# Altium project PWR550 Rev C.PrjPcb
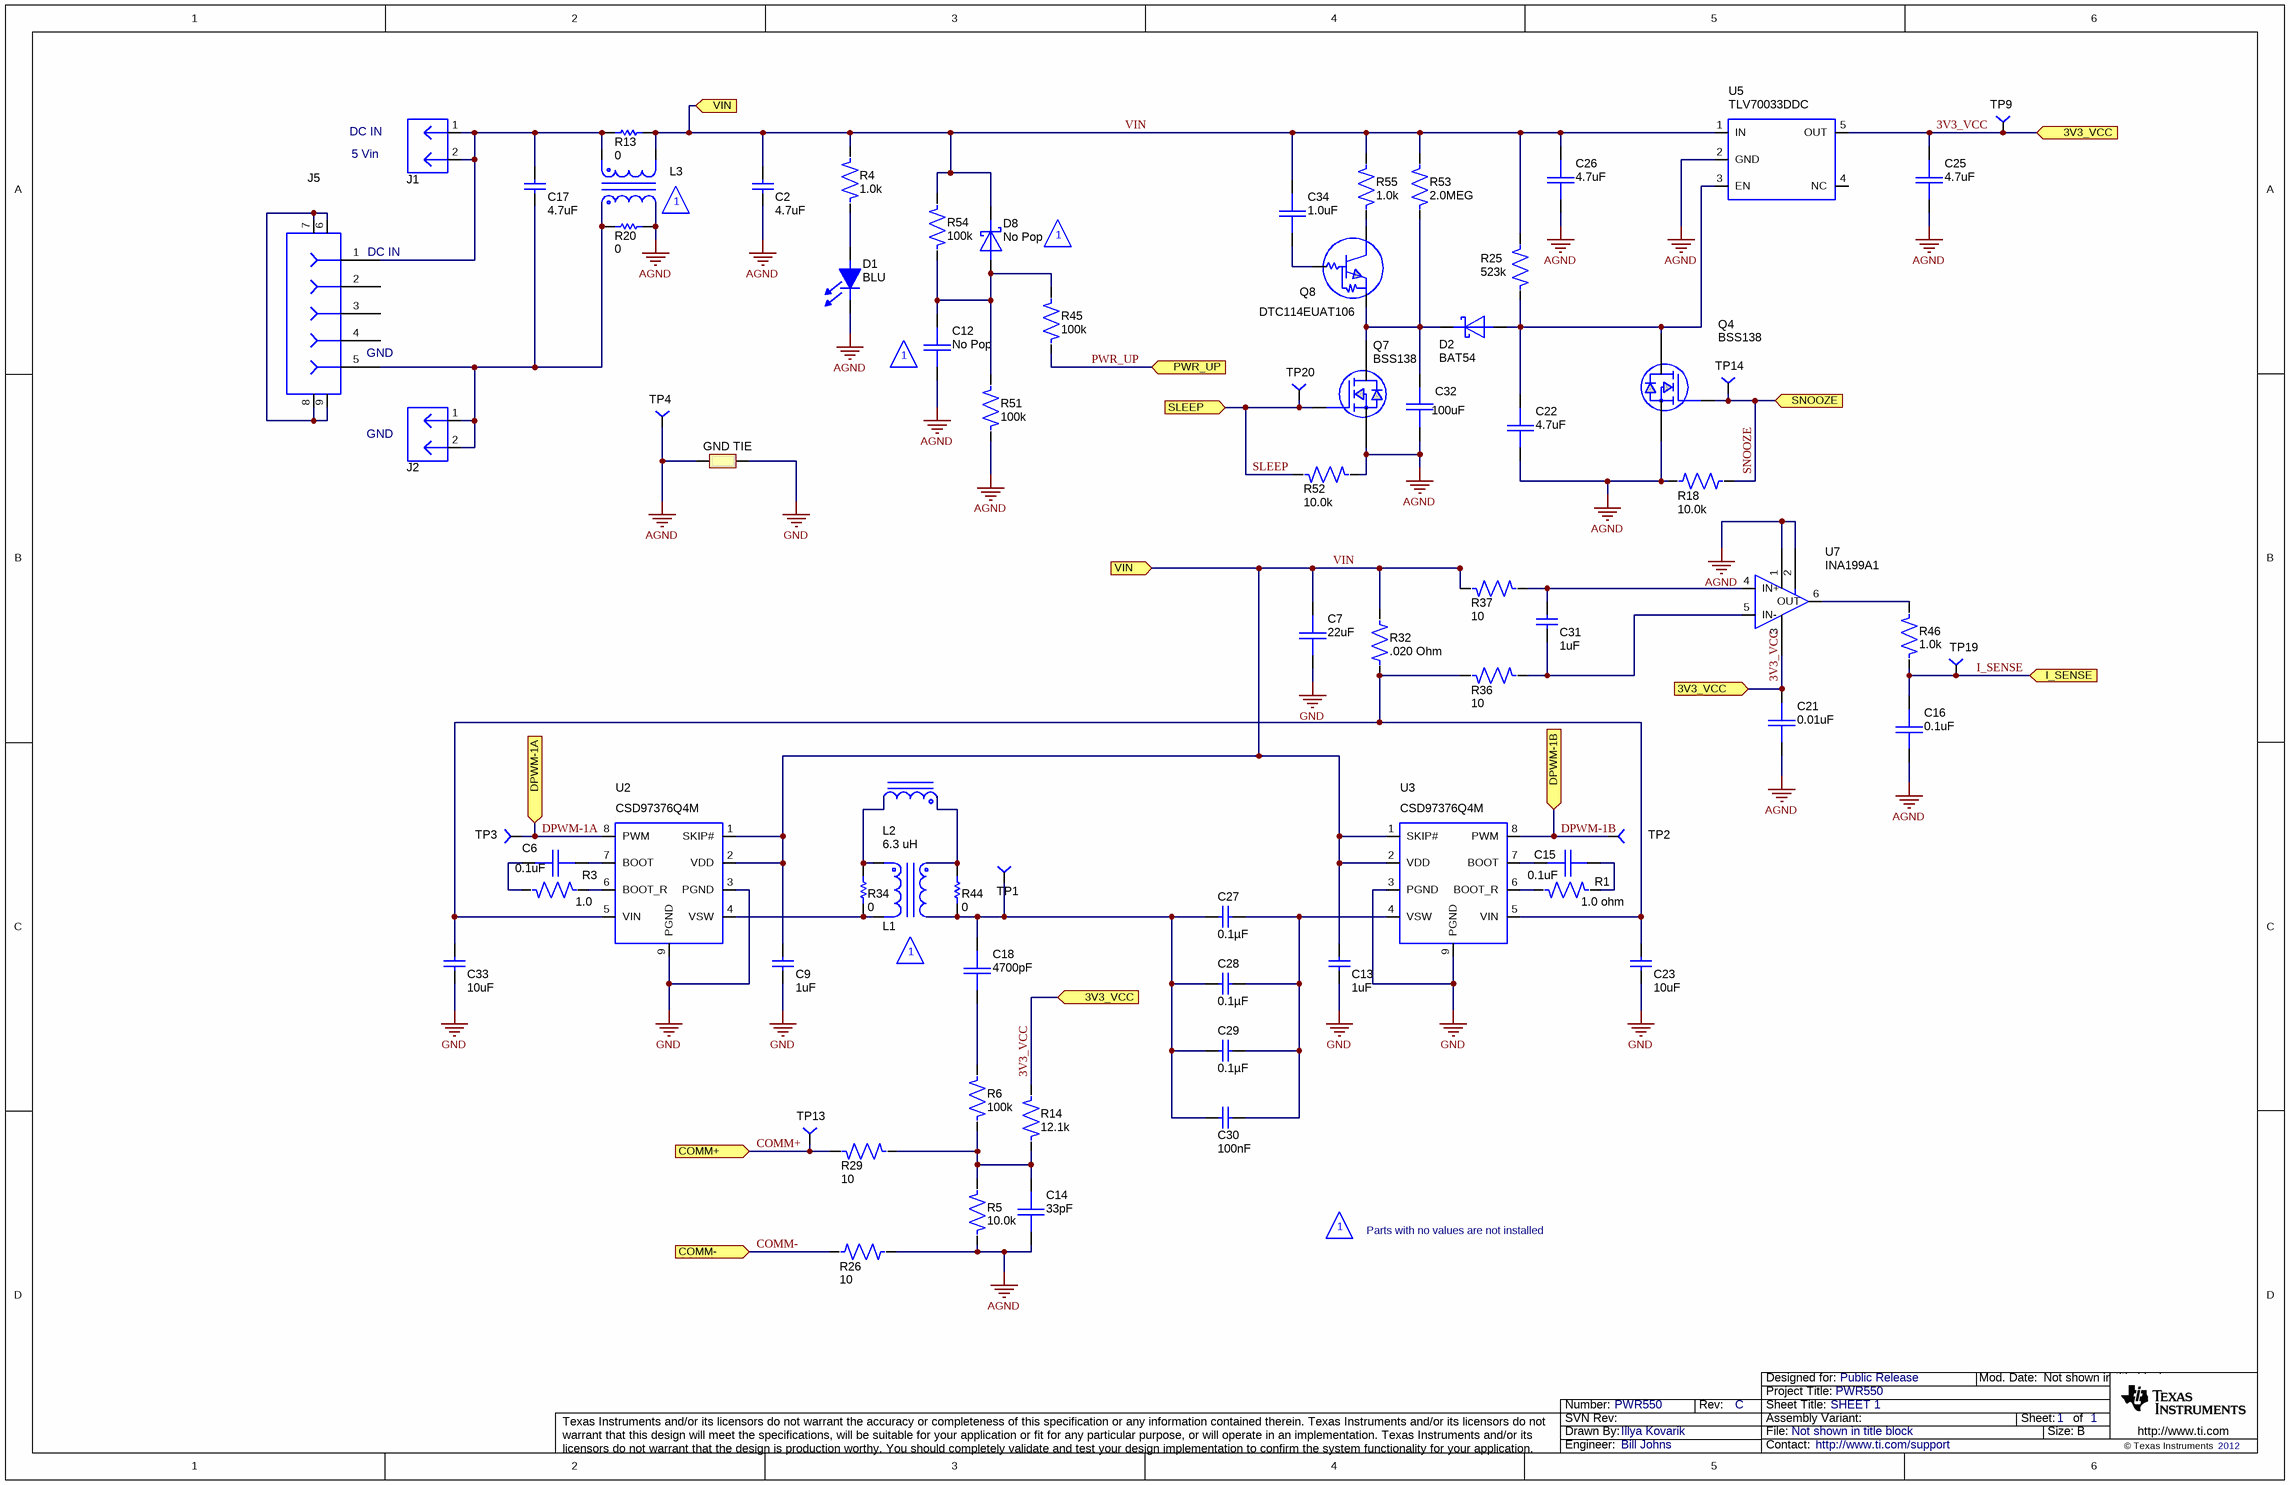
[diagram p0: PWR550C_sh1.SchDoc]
TechSupport: http://www.ti.com/support; SCH_Rev: C; PRJ_Title: PWR550; PRJ_Number: PWR550; PRJ_Engineer: Bill Johns; PRJ_Customer: Public Release; PCB_Rev: A; PCB_Layout: Illya Kovarik; CopyrightYear: 2012
4 sheets, 174 parts. Net scope: flat (ports and power ports of the same name join across sheets).
Board file: PWR550 Rev A.PcbDoc
Sheets:
  PWR550C_sh1.SchDoc
  PWR550C_Hardware.SchDoc
  PWR550C_sh2.SchDoc
  PWR550C_sh3.SchDoc

## Sheet PWR550C_sh1.SchDoc: SHEET 1
size 431 x 279 mm; Date: Not shown in title block; ApprovedBy: Not shown in title block; CheckedBy: Not shown in title block; Author: Not shown in title block; CompanyName: Not shown in title block; DrawnBy: Illya Kovarik; Engineer: Not shown in title block; Organization: Not shown in title block; Address1: Not shown in title block; Address2: Not shown in title block; Address3: Not shown in title block; Address4: Not shown in title block; DocumentNumber: 1; Revision: Use project parameter SCH_Rev; SheetNumber: 1; SheetTotal: 1; PageSetup: Record=PageOptions|CenterHorizontal=True|CenterVertical=True|PrintScale=0.64|XCorrection=1.00|YCorrection=1.00|PrintKind=0|BorderSize=5000000|LeftOffset=0|BottomOffset=0|Orientation=2|PaperLength=1000|PaperWidth=1000|Scale=100|PaperSource=15|PrintQuality=600|MediaType=1|DitherType=10|PaperKind=Letter|PrintScaleMode=1

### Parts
1A1  Net-Tie  [Net-Tie_10mil]  (value not drawn)  (net tie, no BOM)
C2  value 4.7uF  [0805_HV]  (hidden comment: 0805ZD475KAT2A)
C6  value 0.1uF  [C603]  (hidden comment: C0603)
C7  value 22uF  [C1210]  (hidden comment: C1210)
C9  value 1uF  [0603]  (hidden comment: C0603C105K4PACTU)
C12  value No Pop  [C1206]  (hidden comment: C1206)
C13  value 1uF  [0603]  (hidden comment: C0603C105K4PACTU)
C14  value 33pF  [C603]  (hidden comment: C0603)
C15  value 0.1uF  [C603]  (hidden comment: C0603)
C16  value 0.1uF  [C603]  (hidden comment: C0603)
C17  value 4.7uF  [0805_HV]  (hidden comment: 0805ZD475KAT2A)
C18  value 4700pF  [C603]  (hidden comment: C0603)
C21  value 0.01uF  [C603]  (hidden comment: C0603)
C22  value 4.7uF  [C603]  (hidden comment: C0603)
C23  value 10uF  [1210]  (hidden comment: C1210C106K8PACTU)
C25  value 4.7uF  [C603]  (hidden comment: C0603)
C26  value 4.7uF  [C603]  (hidden comment: C0603)
C27  ValueDisplayed: 0.1µF  [1206]  (hidden comment: C3216X7R2A104K)
C28  ValueDisplayed: 0.1µF  [1206]  (hidden comment: C3216X7R2A104K)
C29  ValueDisplayed: 0.1µF  [1206]  (hidden comment: C3216X7R2A104K)
C30  value 100nF  [1210]  (hidden comment: C3225C0G1H104K250AA)
C31  value 1uF  [0603]  (hidden comment: C0603C105K4PACTU)
C32  value 100uF  [C1206]  (hidden comment: C1206)
C33  value 10uF  [1210]  (hidden comment: C1210C106K8PACTU)
C34  value 1.0uF  [C603]  (hidden comment: C0603)
D1  value BLU  [LED-0805]  (hidden comment: D-LED_0805)
D2  value BAT54  [SOT-23]  (hidden comment: D-BAT54)
D8  value No Pop  [SOT-23]  (hidden comment: D-BAT54)
J1  HEADER_1X2  [HDR100_1X2]  (value not drawn)
J2  HEADER_1X2  [HDR100_1X2]  (value not drawn)
J5  CONN_MICRO-USB-B  [CONN_MICRO-USB-B]  (value not drawn)
L1  IND_DLW5BSN_SERIES  [DLW5BSN_SERIES]  (value not drawn)
L2  value 6.3 uH  [IND_TXL05001]  (hidden comment: IND_TXL05001)
L3  IND_DLW5BSN_SERIES  [DLW5BSN_SERIES]  (value not drawn)
Q4  BSS138  [SOT-23]
Q7  BSS138  [SOT-23]
Q8  DTC114EUAT106  [SOT-323]
R1  value 1.0 ohm  [R603]  (hidden comment: R0603_1%)
R3  value 1.0  [R603]  (hidden comment: R0603_1%)
R4  value 1.0k  [R0603]  (hidden comment: R0603)
R5  value 10.0k  [R603]  (hidden comment: R0603_1%)
R6  value 100k  [R603]  (hidden comment: R0603_1%)
R13  value 0  [1206L]  (hidden comment: CRCW12060000Z0EA)
R14  value 12.1k  [R603]  (hidden comment: R0603_1%)
R18  value 10.0k  [R603]  (hidden comment: R0603_1%)
R20  value 0  [1206L]  (hidden comment: CRCW12060000Z0EA)
R25  value 523k  [R603]  (hidden comment: R0603_1%)
R26  value 10  [R603]  (hidden comment: R0603_1%)
R29  value 10  [R603]  (hidden comment: R0603_1%)
R32  value .020 Ohm  [R0805]  (hidden comment: R0805)
R34  value 0  [1206L]  (hidden comment: CRCW12060000Z0EA)
R36  value 10  [R603]  (hidden comment: R0603_1%)
R37  value 10  [R603]  (hidden comment: R0603_1%)
R44  value 0  [1206L]  (hidden comment: CRCW12060000Z0EA)
R45  value 100k  [R603]  (hidden comment: R0603_1%)
R46  value 1.0k  [R603]  (hidden comment: R0603_1%)
R51  value 100k  [R603]  (hidden comment: R0603_1%)
R52  value 10.0k  [R603]  (hidden comment: R0603_1%)
R53  value 2.0MEG  [R603]  (hidden comment: R0603_1%)
R54  value 100k  [R603]  (hidden comment: R0603_1%)
R55  value 1.0k  [R603]  (hidden comment: R0603_1%)
TP1  TP-5012-WHITE  [TH-63]  (value not drawn)
TP2  TP_1045  [TP_1045]  (value not drawn)
TP3  TP_1045  [TP_1045]  (value not drawn)
TP4  TP-5011-BLACK  [TH-63]  (value not drawn)
TP9  TP_40_SMT  [TP_40_SMT]  (value not drawn)
TP13  TP_1045  [TP_1045]  (value not drawn)
TP14  TP_40_SMT  [TP_40_SMT]  (value not drawn)
TP19  TP_1045  [TP_1045]  (value not drawn)
TP20  TP_40_SMT  [TP_40_SMT]  (value not drawn)
U2  value CSD97376Q4M  [QFN4.5X3.5MM_8PWD]  (hidden comment: CSD97376CQ4M)
U3  value CSD97376Q4M  [QFN4.5X3.5MM_8PWD]  (hidden comment: CSD97376CQ4M)
U5  TLV70033DDC  [DBV-5]
U7  value INA199A1  [DCK-6]  (hidden comment: INA21XDCK)

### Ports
3V3_VCC, COMM+, COMM-, DPWM-1A, DPWM-1B, I_SENSE, PWR_UP, SLEEP, SNOOZE, VIN

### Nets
AGND: 1A1.2 C2.2 C12.1 C14.1 C16.1 C21.1 C22.1 C25.1 C26.1 C32.2 D1.1(C) L3.3 Q4.2(S) Q7.2(S) R5.1 R18.1 R20.2 R26.2 R51.1 R52.1 TP4.1 U5.2(GND) U7.1(REF) U7.2(GND)
GND: 1A1.1 C7.1 C9.2 C13.2 C23.2 C33.2 U2.3(PGND) U2.9(PGND) U3.3(PGND) U3.9(PGND)
3V3_VCC: C21.2 C25.2 R14.2 TP9.1 U5.5(OUT) U7.3(V+) ; port 3V3_VCC
COMM+: R29.2 TP13.1 ; port COMM+
COMM-: R26.1 ; port COMM-
DPWM-1A: TP3.1 U2.8(PWM) ; port DPWM-1A
DPWM-1B: TP2.1 U3.8(PWM) ; port DPWM-1B
I_SENSE: C16.2 R46.1 TP19.1 ; port I_SENSE
PWR_UP: R45.1 ; port PWR_UP
SLEEP: Q7.1(G) R52.2 TP20.1 ; port SLEEP
SNOOZE: Q4.1(G) R18.2 TP14.1 ; port SNOOZE
VIN: C2.1 C7.2 C9.1 C13.1 C26.2 C34.2 D8.3(C) L3.2 R4.2 R13.2 R25.2 R32.2 R37.2 R53.2 R54.2 R55.2 U2.1(SKIP#) U2.2(VDD) U3.1(SKIP#) U3.2(VDD) U5.1(IN) ; port VIN
NetC6_1: C6.1 U2.7(BOOT)
NetC6_2: C6.2 R3.1
NetC12_2: C12.2 D8.1(A) R45.2 R51.2 R54.1
NetC14_2: C14.2 R5.2 R6.1 R14.1 R29.1
NetC15_1: C15.1 R1.2
NetC15_2: C15.2 U3.7(BOOT)
NetC17_1: C17.1 J1.1 J1.2 J5.1 L3.1 R13.1
NetC17_2: C17.2 J2.1 J2.2 J5.5 L3.4 R20.1
NetC18_1: C18.1 R6.2
NetC18_2: C18.2 C27.2 C28.2 C29.2 C30.2 L1.3 R44.1 TP1.1
NetC22_2: C22.2 D2.1(A) Q4.3(D) R25.1 U5.3(EN)
NetC23_1: C23.1 C33.1 R32.1 R36.2 U2.5(VIN) U3.5(VIN)
NetC27_1: C27.1 C28.1 C29.1 C30.1 U3.4(VSW)
NetC31_1: C31.1 R37.1 U7.4(IN+)
NetC31_2: C31.2 R36.1 U7.5(IN-)
NetC32_1: C32.1 D2.3(C) Q7.3(D) Q8.1(GND) R53.1
NetC34_1: C34.1 Q8.2(IN)
NetD1_2: D1.2(A) R4.1
NetJ5_6: J5.6 J5.7 J5.8 J5.9
NetL1_1: L1.1 L2.2 R34.2
NetL1_2: L1.2 R34.1 U2.4(VSW)
NetL1_4: L1.4 L2.1 R44.2
NetQ8_3: Q8.3(OUT) R55.1
NetR1_1: R1.1 U3.6(BOOT_R)
NetR3_2: R3.2 U2.6(BOOT_R)
NetR46_2: R46.2 U7.6(OUT)

Not connected (* = marked no-connect by the designer): J5 2 3 4; U5 4(NC)

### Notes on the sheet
- DC IN
- 5 Vin
- (near L3) 1
- (near J5) DC IN
- 1
- (near J5) GND
- (near C12) 1
- GND
- (near 1A1) GND TIE
- (near L1) 1
- Parts with no values are not installed

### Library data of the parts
1A1 = Net-Tie: Single point connection between nets.; SymbolCreator: codlsc
C2 C17 = 0805ZD475KAT2A: CAP, CERM, 4.7uF, 10V, +/-10%, X5R, 0805; Manufacturer: AVX; Polarized: N; CompType: Capacitor; U/M: EA; Cap_F: 0.0000047; Tolerance_%: 10; ESR_Ohm: 0.007; Value1: 0.007 ohm; TaMin_C: -55; TaMax_C: 85; Cap_Case: 0805
C6 C15 C16 = C0603: Capacitor, Ceramic, 0.1UF 50V 10% X7R 0603; Manufacturer: TDK; PartNumber: C1608X7R1H104K080AA; Area: 5650
C7 = C1210: Capacitor, Ceramic, 22UF 25V 10% X5R 1210; Manufacturer: Murata; PartNumber: GRM32ER61E226KE15L; Alternate Manufacturer: Digi-Key; Alternate PartNumber: 490-3889-1; Area: 28000
C9 C13 C31 = C0603C105K4PACTU: CAP, CERM, 1uF, 16V, +/-10%, X5R, 0603; Manufacturer: Kemet; Polarized: N; CompType: Capacitor; U/M: EA; Cap_F: 0.000001; Tolerance_%: 10; Value1: Unknown; VDC_V: 16; TaMin_C: -55; TaMax_C: 85
C12 = C1206: Capacitor, Ceramic Chip, 2.2UF 16V 10% X7R 1206; Manufacturer: TDK; PartNumber: Open; Alternate Manufacturer: Digi-Key; Area: 15390
C14 = C0603: Capacitor, Ceramic, 33PF 50V 5% NP0 0603; Manufacturer: TDK; PartNumber: C1608C0G1H330J080AA; Alternate Manufacturer: Digi-Key; Alternate PartNumber: 445-1275-1; Area: 5650
C18 = C0603: Capacitor, Ceramic, 4700pF, 50V, X7R, 10%; Manufacturer: TDK; PartNumber: C1608C0G1H472J080AA; Alternate Manufacturer: Digi-Key; Alternate PartNumber: 445-7400-2-ND; Area: 5650
C21 = C0603: Capacitor, Ceramic, 0.01uF, 50V, X7R, 10%; Manufacturer: TDK; PartNumber: C1608X7R1H103K080AA; Alternate Manufacturer: Digi-Key; Alternate PartNumber: 445-1311-1; Area: 5650
C22 = C0603: Capacitor, Ceramic,  4.7UF 10V 20% X5R 060; Manufacturer: TDK; PartNumber: CGB3B1X5R1A475M055AC; Area: 5650
C23 C33 = C1210C106K8PACTU: CAP, CERM, 10uF, 10V, +/-10%, X5R, 1210; Manufacturer: Kemet; Polarized: N; CompType: Capacitor; U/M: EA; Cap_F: 0.00001; Tolerance_%: 10; ESR_Ohm: 0.008; Value1: 0.008 ohm; IRMS_A: 6.9; TaMin_C: -55; TaMax_C: 85
C25 = C0603: Capacitor, Ceramic, 4.7UF 10V 20% X5R 0603; Manufacturer: TDK; PartNumber: CGB3B1X5R1A475M055AC; Area: 5650
C26 = C0603: Capacitor, Ceramic,  4.7UF 10V 20% X5R 0603; Manufacturer: TDK; PartNumber: CGB3B1X5R1A475M055AC; Area: 5650
C27-C29 = C3216X7R2A104K: CAP, CERM, 0.1uF, 100V, +/-10%, X7R, 1206; Manufacturer: TDK; VDC_V: 100; Tolerance_%: 10; Polarized: N; CompType: Capacitor; U/M: EA; Cap_F: 0.0000001; ESR_Ohm: 0.0259; Value1: 0.0259 ohm; IRMS_A: 1.5; TaMin_C: -55; TaMax_C: 125
C30 = VJ1210Y104KBBAT4X: CAP CER 0.1UF 50V 10% NP0 1210; Manufacturer: TDK Corporation; Alternate Manufacturer: Kemet; Alternate PartNumber: C1210C104J1GACTU; TempCo: C0G, NP0
C32 = C1206: Capacitor, Ceramic Chip, 100UF 6.3V 20% X5R 1206; Manufacturer: TDK; PartNumber: C3216X5R0J107M160AB; Alternate PartNumber: 445-6008-1; Area: 15390
C34 = C0603: Capacitor, Ceramic, 1UF 16V 10% X7R 0603; Manufacturer: TDK; PartNumber: C1608X7R1C105K080AC; Area: 5650
D1 = D-LED_0805: Diode. LED 2X1.2MM 470NM BL WTR CLR SMD; PartNumber: APT2012QBC/D; Manufacturer: Kingbright Corp; Alternate PartNumber: 754-1437-1-ND; Alternate Manufacturer: Digi-Key; Area: 9.85 mm
D2 = D-BAT54: Diode, Schottky, 200-mA, 30-V; Manufacturer: Vishay-Liteon; Second Source: C:\program files\p-cad 2004\pcad_pdf's\bat54v.pdf; Area: 14105
D8 = D-BAT54: Diode, Schottky, 200-mA, 30-V; PartNumber: Open; Manufacturer: Vishay-Liteon; Second Source: C:\program files\p-cad 2004\pcad_pdf's\bat54v.pdf; Area: 14105
J1 J2 = HEADER_1X2: Header, Male 2-pin, 100mil spacing,; Manufacturer: Sullins; PartNumber: PEC02SAAN; Second Source: C:\program files\p-cad 2004\pcad_pdf's\pec36saan.pdf; area: 20000
J5 = CONN_MICRO-USB-B: Connector, SMT, Micro USB-B; PartNumber: ZX62D-B-5P8; Manufacturer: Hirose Electric Co; Alternate Manufacturer: Digi-Key; Alternate PartNumber: H11494CT-ND; Area: 50.76 mm; Second Source: C:\program files\p-cad 2004\pcad_pdf's\Micro_USB
L1 L3 = IND_DLW5BSN_SERIES: Inductor, Toroid, yyA, zzmilliohm; Manufacturer: muRata; PartNumber: DLW5BSNxxxSQ2; Second Source: C:\program files\p-cad 2004\pcad_pdf's\DLW5BSN series.pdf; Area: 59800
L2 = IND_TXL05001: TX Coil; PartNumber: 760-308-111; Manufacturer: Wurth Elektronik; Area: 3481.0 mm; Second Source: C:\program files\p-cad2004pcad_pdf's\TXL05001.pdf; PCB DECAL: WPC A11
Q4 Q7 = TR-BSS138: MOSFET, Nch, 50V, 0.22A, 3.5 Ohm; Manufacturer: Fairchild; Area: 14105
Q8 = TR-DTC114EUA: Transistor, Digital NPN, 50 V, 100 mA; Manufacturer: Rohm; Area: 23010
R1 R3 = R0603_1%: Resistor, Chip, 1.0 OHM 1/10W 5% 0603 SMD; Manufacturer: Yageo; PartNumber: RC0603JR-071RL; Alternate Manufacturer: Digi-Key; Alternate PartNumber: 311-1.0GRCT; Area: 9100
R4 = R0603: Resistor, Chip, 1.00K OHM 1/10W 1% 0603 SMD; PartNumber: RC0603FR-071KL; Manufacturer: Std; Alternate Manufacturer: Digi-Key; Alternate PartNumber: 311-1.00KH; POPULATE?: YES; RATING: 0.1W; DIGI_KEY: 311-1.00KHRCT-ND; Second Source: C:\program files\p-cad 2004\pcad_pdf's\1n5333b-88b.pdf; Area: 2800
R5 R18 R52 = R0603_1%: RES 10.0K OHM 1/10W 1% 0603 SMD; Manufacturer: Yageo; PartNumber: RC0603FR-0710KL; Area: 9100
R6 R45 R51 R54 = R0603_1%: Resistor, Chip, 100K OHM 1/10W 1% 0603 SMD; Manufacturer: Yageo; PartNumber: RC0603FR-07100KL; Alternate Manufacturer: Digi-Key; Alternate PartNumber: 311-100KHRTR; Area: 9100
R13 R20 R34 R44 = CRCW12060000Z0EA: RES, 0 ohm, 5%, 0.25W, 1206; Manufacturer: Vishay-Dale; CompType: Resistor; Value_Code: 0000; Tolerance_%: 5; Power_W: 0.25; VDC_V: 200; TempCo: 200 ppm/C; EIA_Code: E24; U/M: EA
R14 = R0603_1%: Resistor, Chip,  12.1K OHM 1/10W 1% 0603 SMD; Manufacturer: Yageo; PartNumber: RC0603FR-0712K1L; Alternate Manufacturer: Digi-Key; Alternate PartNumber: 311-12.1KHRCT; Area: 9100
R25 = R0603_1%: Resistor, Chip, 523K OHM 1/10W 1% 0603 SMD; Manufacturer: Yageo; PartNumber: RC0603FR-07523KL; Alternate Manufacturer: Digi-Key; Alternate PartNumber: 311-523KHRCT; Area: 9100
R26 = R0603_1%: Resistor, Chip,  10 OHM 1/10W 5% 0603 SMD; Manufacturer: Yageo; PartNumber: RC0603JR-0710RL; Alternate Manufacturer: Digi-Key; Alternate PartNumber: 311-10GR; Area: 9100
R29 R36 R37 = R0603_1%: Resistor, Chip,  10 OHM 1/10W 5% 0603 SMD; Manufacturer: Yageo; PartNumber: RC0603JR-0710RL; Alternate Manufacturer: Digi-Key; Alternate PartNumber: 311-10GRCT; Area: 9100
R32 = R0805: Resistor, Chip, 0.02 OHM 1/2W 1% 0805 SMD; Manufacturer: Panasonic Electronic Components; PartNumber: ERJ-6BWFR020V; Alternate Manufacturer: Digi-Key; Alternate PartNumber: P.02AQCT-ND; Area: 10560
R46 R55 = R0603_1%: Resistor, Chip, 1.00K OHM 1/10W 1% 0603 SMD; Manufacturer: Yageo; PartNumber: RC0603FR-071KL; Alternate Manufacturer: Digi-Key; Alternate PartNumber: 311-1.00KH; Alternate PartNumber: 311-1.00KHRCT-ND; Area: 9100
R53 = R0603_1%: Resistor, Chip,  2.00M OHM 1/10W 1% 0603 SMD; Manufacturer: Yageo; PartNumber: RC0603FR-072ML; Alternate Manufacturer: Digi-Key; Alternate PartNumber: 311-2.00MHRCT; Area: 9100
TP1 = TP-5012-WHITE: Test Point, White, Thru Hole; Manufacturer: Keystone; PartNumber: 5012; Second Source: C:\program files\p-cad 2004\pcad_pdf's\Keystone-SMT-TH_Test point.pdf
TP2 TP3 TP13 = TP_1045: Post, Wirewrap, 0.043 press-fit, For 0.015-0.025 pins; Manufacturer: Mill-Max; PartNumber: 1045-3-17-15-30-14-02-0; area: 0.001 inch; Value: Open; Second Source: C:\program files\p-cad 2004\pcad_pdf's\Mill-Max_1045.pdf
TP4 = TP-5011-BLACK: Test Point, Black, Thru Hole; Manufacturer: Keystone; PartNumber: 5011; Second Source: C:\program files\p-cad 2004\pcad_pdf's\Keystone-SMT-TH_Test point.pdf
TP9 TP14 TP20 = TP_40_SMT: Test point, 40 mil SMT; Manufacturer: None
TP19 = TP_1045: Post, Wirewrap, 0.043 press-fit, For 0.015-0.025 pins; Manufacturer: Mill-Max; PartNumber: 1045-3-17-15-30-14-02-0; area: 0.001 inch; Second Source: C:\program files\p-cad 2004\pcad_pdf's\Mill-Max_1045.pdf
U2 U3 = CSD97374CQ4M: IC, Synchronous Buck NexFETPower Stage; Manufacturer: TI; Alternate Manufacturer: None; Second Source: C:\program files\p-cad 2004\pcad_pdf's\CSD97374Q4M rev1 1.doc; Area: 23 mm
U5 = TLV713XXDBV: IC REG LDO 3.3V 200mA SOT-23-5; Manufacturer: TI; Alternate Manufacturer: Digi-Key; Alternate Manufacturer: None; Alternate PartNumber: 296-25276-1-ND; Area: 23200; Second Source: C:\program files\p-cad 2004\pcad_pdf's\TLV713 One Page.pptx
U7 = INA21XDCK: IC,  Current Monitor, High or Low Side Measurement,  Bi-Directional Zerø-Drift Series; PartNumber: INA199A1DCKR; Manufacturer: TI; Alternate Manufacturer: None; Second Source: C:\program files\p-cad 2004\pcad_pdf's\ina214.pdf; Area: 18600

## Sheet PWR550C_Hardware.SchDoc: bq500212AEVM
size 431 x 279 mm; Date: Not shown in title block; ApprovedBy: Not shown in title block; CheckedBy: Not shown in title block; Author: Not shown in title block; CompanyName: Not shown in title block; DrawnBy: Krypton; Engineer: Bill Johns; Organization: Not shown in title block; Address1: Not shown in title block; Address2: Not shown in title block; Address3: Not shown in title block; Address4: Not shown in title block; DocumentNumber: 1; Revision: Use project parameter SCH_Rev; SheetNumber: 1; SheetTotal: 1; PageSetup: Record=PageOptions|CenterHorizontal=True|CenterVertical=True|PrintScale=0.64|XCorrection=1.00|YCorrection=1.00|PrintKind=0|BorderSize=5000000|LeftOffset=0|BottomOffset=0|Orientation=2|PaperLength=1000|PaperWidth=1000|Scale=100|PaperSource=15|PrintQuality=600|MediaType=1|DitherType=10|PaperKind=Letter|PrintScaleMode=1
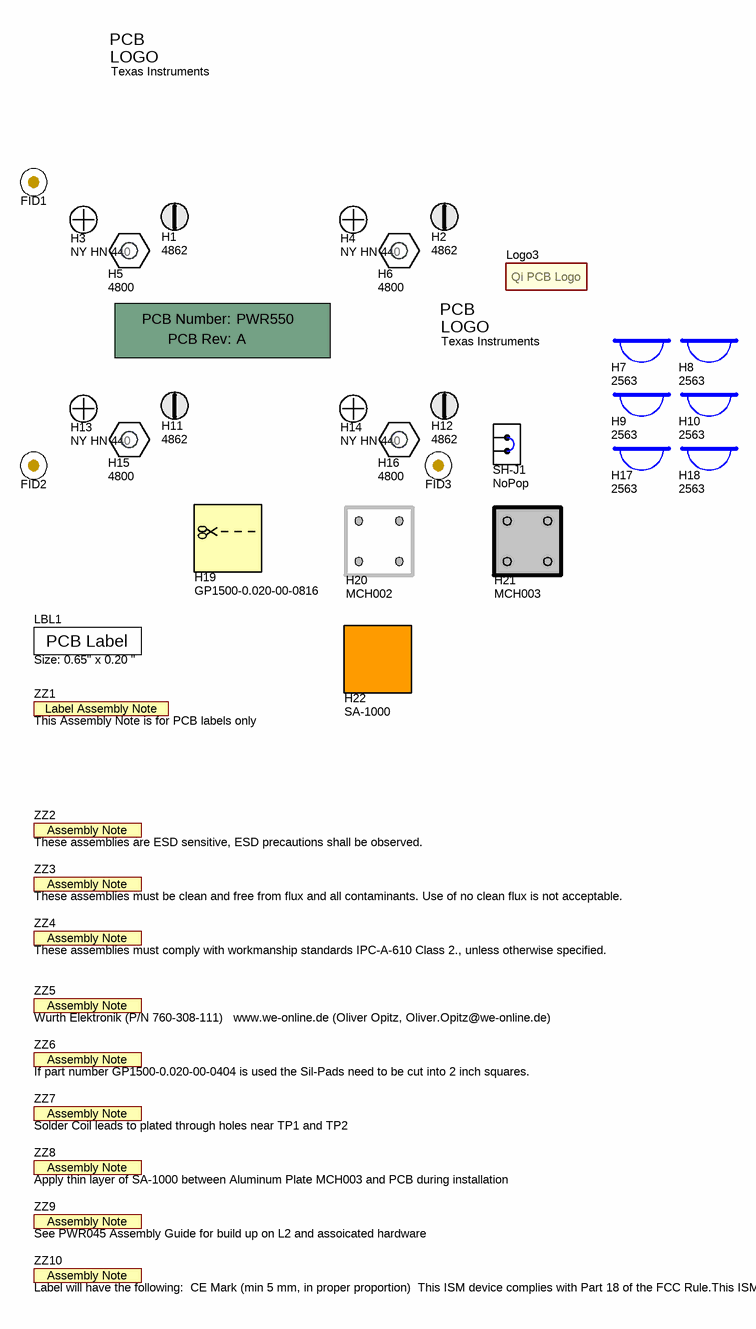
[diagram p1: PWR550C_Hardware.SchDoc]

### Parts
!PCB  Printed Circuit Board  (value not drawn)  (mechanical)
FID1  Fiducial  [Fiducial10-20]  (value not drawn)
FID2  Fiducial  [Fiducial10-20]  (value not drawn)
FID3  Fiducial  [Fiducial10-20]  (value not drawn)
H1  4862
H2  4862
H3  NY HN 440
H4  NY HN 440
H5  4800
H6  4800
H7  2563
H8  2563
H9  2563
H10  2563
H11  4862
H12  4862
H13  NY HN 440
H14  NY HN 440
H15  4800
H16  4800
H17  2563
H18  2563
H19  GP1500-0.020-00-0816
H20  MCH002
H21  MCH003
H22  SA-1000
LBL1  Size: 0.65" x 0.20 "  [Label_650x200]
Logo1  Texas Instruments  [TI_Stacked_SolderMask_Small]  (no BOM)
Logo2  Texas Instruments  [TI_Horizontal_Overlay_Medium]  (no BOM)
Logo3  Silk  [QI Logo]  (value not drawn)
SH-J1  value NoPop  [SNT-100-BK-G]  (hidden comment: SNT-100-BK-G)
ZZ1  This Assembly Note is for PCB labels only  [AssemblyNoteLabel]  (no BOM)
ZZ2  These assemblies are ESD sensitive, ESD precautions shall be observed.  [AssemblyNote]  (no BOM)
ZZ3  These assemblies must be clean and free from flux and all contaminants. Use of no clean flux is not acceptable.  [AssemblyNote]  (no BOM)
ZZ4  These assemblies must comply with workmanship standards IPC-A-610 Class 2., unless otherwise specified.  [AssemblyNote]  (no BOM)
ZZ5  Wurth Elektronik (P/N 760-308-111)   www.we-online.de (Oliver Opitz, Oliver.Opitz@we-online.de)  [AssemblyNote]  (no BOM)
ZZ6  If part number GP1500-0.020-00-0404 is used the Sil-Pads need to be cut into 2 inch squares.  [AssemblyNote]  (no BOM)
ZZ7  Solder Coil leads to plated through holes near TP1 and TP2  [AssemblyNote]  (no BOM)
ZZ8  Apply thin layer of SA-1000 between Aluminum Plate MCH003 and PCB during installation  [AssemblyNote]  (no BOM)
ZZ9  See PWR045 Assembly Guide for build up on L2 and assoicated hardware  [AssemblyNote]  (no BOM)
ZZ10  Label will have the following:  CE Mark (min 5 mm, in proper proportion)  This ISM device complies with Part 18 of the FCC Rule.This ISM device complies with Canadian ICES-001. Cet appareil ISM est conforme à la norme NMB-001 du Canada.  [AssemblyNote]  (no BOM)

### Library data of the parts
!PCB = PCB: Manufacturer: Any; PartNumber: PWR550; SymbolCreator: a0412235
FID1-FID3 = Fiducial: Fiducial mark.  There is nothing to buy or mount.; SymbolCreator: codlsc
H1 H2 H11 H12 = Screw steel: Screw steel zinc, flathead 4-40 machine, 0.250; Manufacturer: Pomona Electronics
H3 H4 H13 H14 = Nut #4-40: Nut #4-40 Hex Nylon; Manufacturer: B&F Fastener Supply
H5 H6 H15 H16 = 4800: STANDOFF M/F HEX 4-40 NYL .250"L; Manufacturer: Keystone Electronics; Thread/Screw/Hole Size: 4-40 Thread; Between Board Height: 0.250" (6.35mm) 1/4"
H7-H10 H17 H18 = 2563: Mounting Feet, 0.25" tall; Manufacturer: Voltrex
H19 = GP1500: Sil-Pad  Cut to Size 2.0" Square; Manufacturer: Bergquist; Alternate PartNumber: GP1500-0.020-00-0404
H20 = MCH002: Cover, Plastic Polycarbonate, 2.75" Square, 0.93 thick; Manufacturer: Any
H21 = MCH003: Plate, aluminum  2.0" x 2.0" x .062"; Manufacturer: Any
H22 = SA-1000: Adhesive, Thermally Conductive Silicone; Manufacturer: Bergquist
LBL1 = THT-14-423-10: Thermal Transfer Printable Labels, 0.650" W x 0.200" H - 10,000 per roll; Manufacturer: Brady; SymbolCreator: a0412235; CompType: Label
Logo1 Logo2 = TI_Logo: Texas Instrument Corporate Signature; SymbolCreator: codlsc
Logo3 = Qi PCB Logo: SymbolVersion: use current date i.e. 2008-05-20; SymbolCreator: Use a-id; CompType: Used in some BOM reports.  Useful for finding later.; U/M: EA, IN, or GM
SH-J1 = SNT-100-BK-G: Shunt, 100mil, Gold plated, Black; Manufacturer: Samtec, Inc.; Alternate Manufacturer: 3M; Alternate PartNumber: 969102-0000-DA; Note: You can "mate" this to a header by matching the designator.  i.e. use SH-J3 for header J3
ZZ1 = AssemblyNoteLabel: SymbolCreator: a0412235
ZZ2-ZZ10 = AssemblyNote: SymbolCreator: codlsc

## Sheet PWR550C_sh2.SchDoc: SHEET 2
size 431 x 279 mm; Date: Not shown in title block; ApprovedBy: Not shown in title block; CheckedBy: Not shown in title block; Author: Not shown in title block; CompanyName: Not shown in title block; DrawnBy: Illya Kovarik; Engineer: Not shown in title block; Organization: Not shown in title block; Address1: Not shown in title block; Address2: Not shown in title block; Address3: Not shown in title block; Address4: Not shown in title block; DocumentNumber: 1; Revision: Use project parameter SCH_Rev; SheetNumber: 1; SheetTotal: 1; PageSetup: Record=PageOptions|CenterHorizontal=True|CenterVertical=True|PrintScale=1.00|XCorrection=1.00|YCorrection=1.00|PrintKind=0|BorderSize=5000000|LeftOffset=0|BottomOffset=0|Orientation=2|PaperLength=1000|PaperWidth=1000|Scale=100|PaperSource=15|PrintQuality=600|MediaType=1|DitherType=10|PaperKind=Letter|PrintScaleMode=1
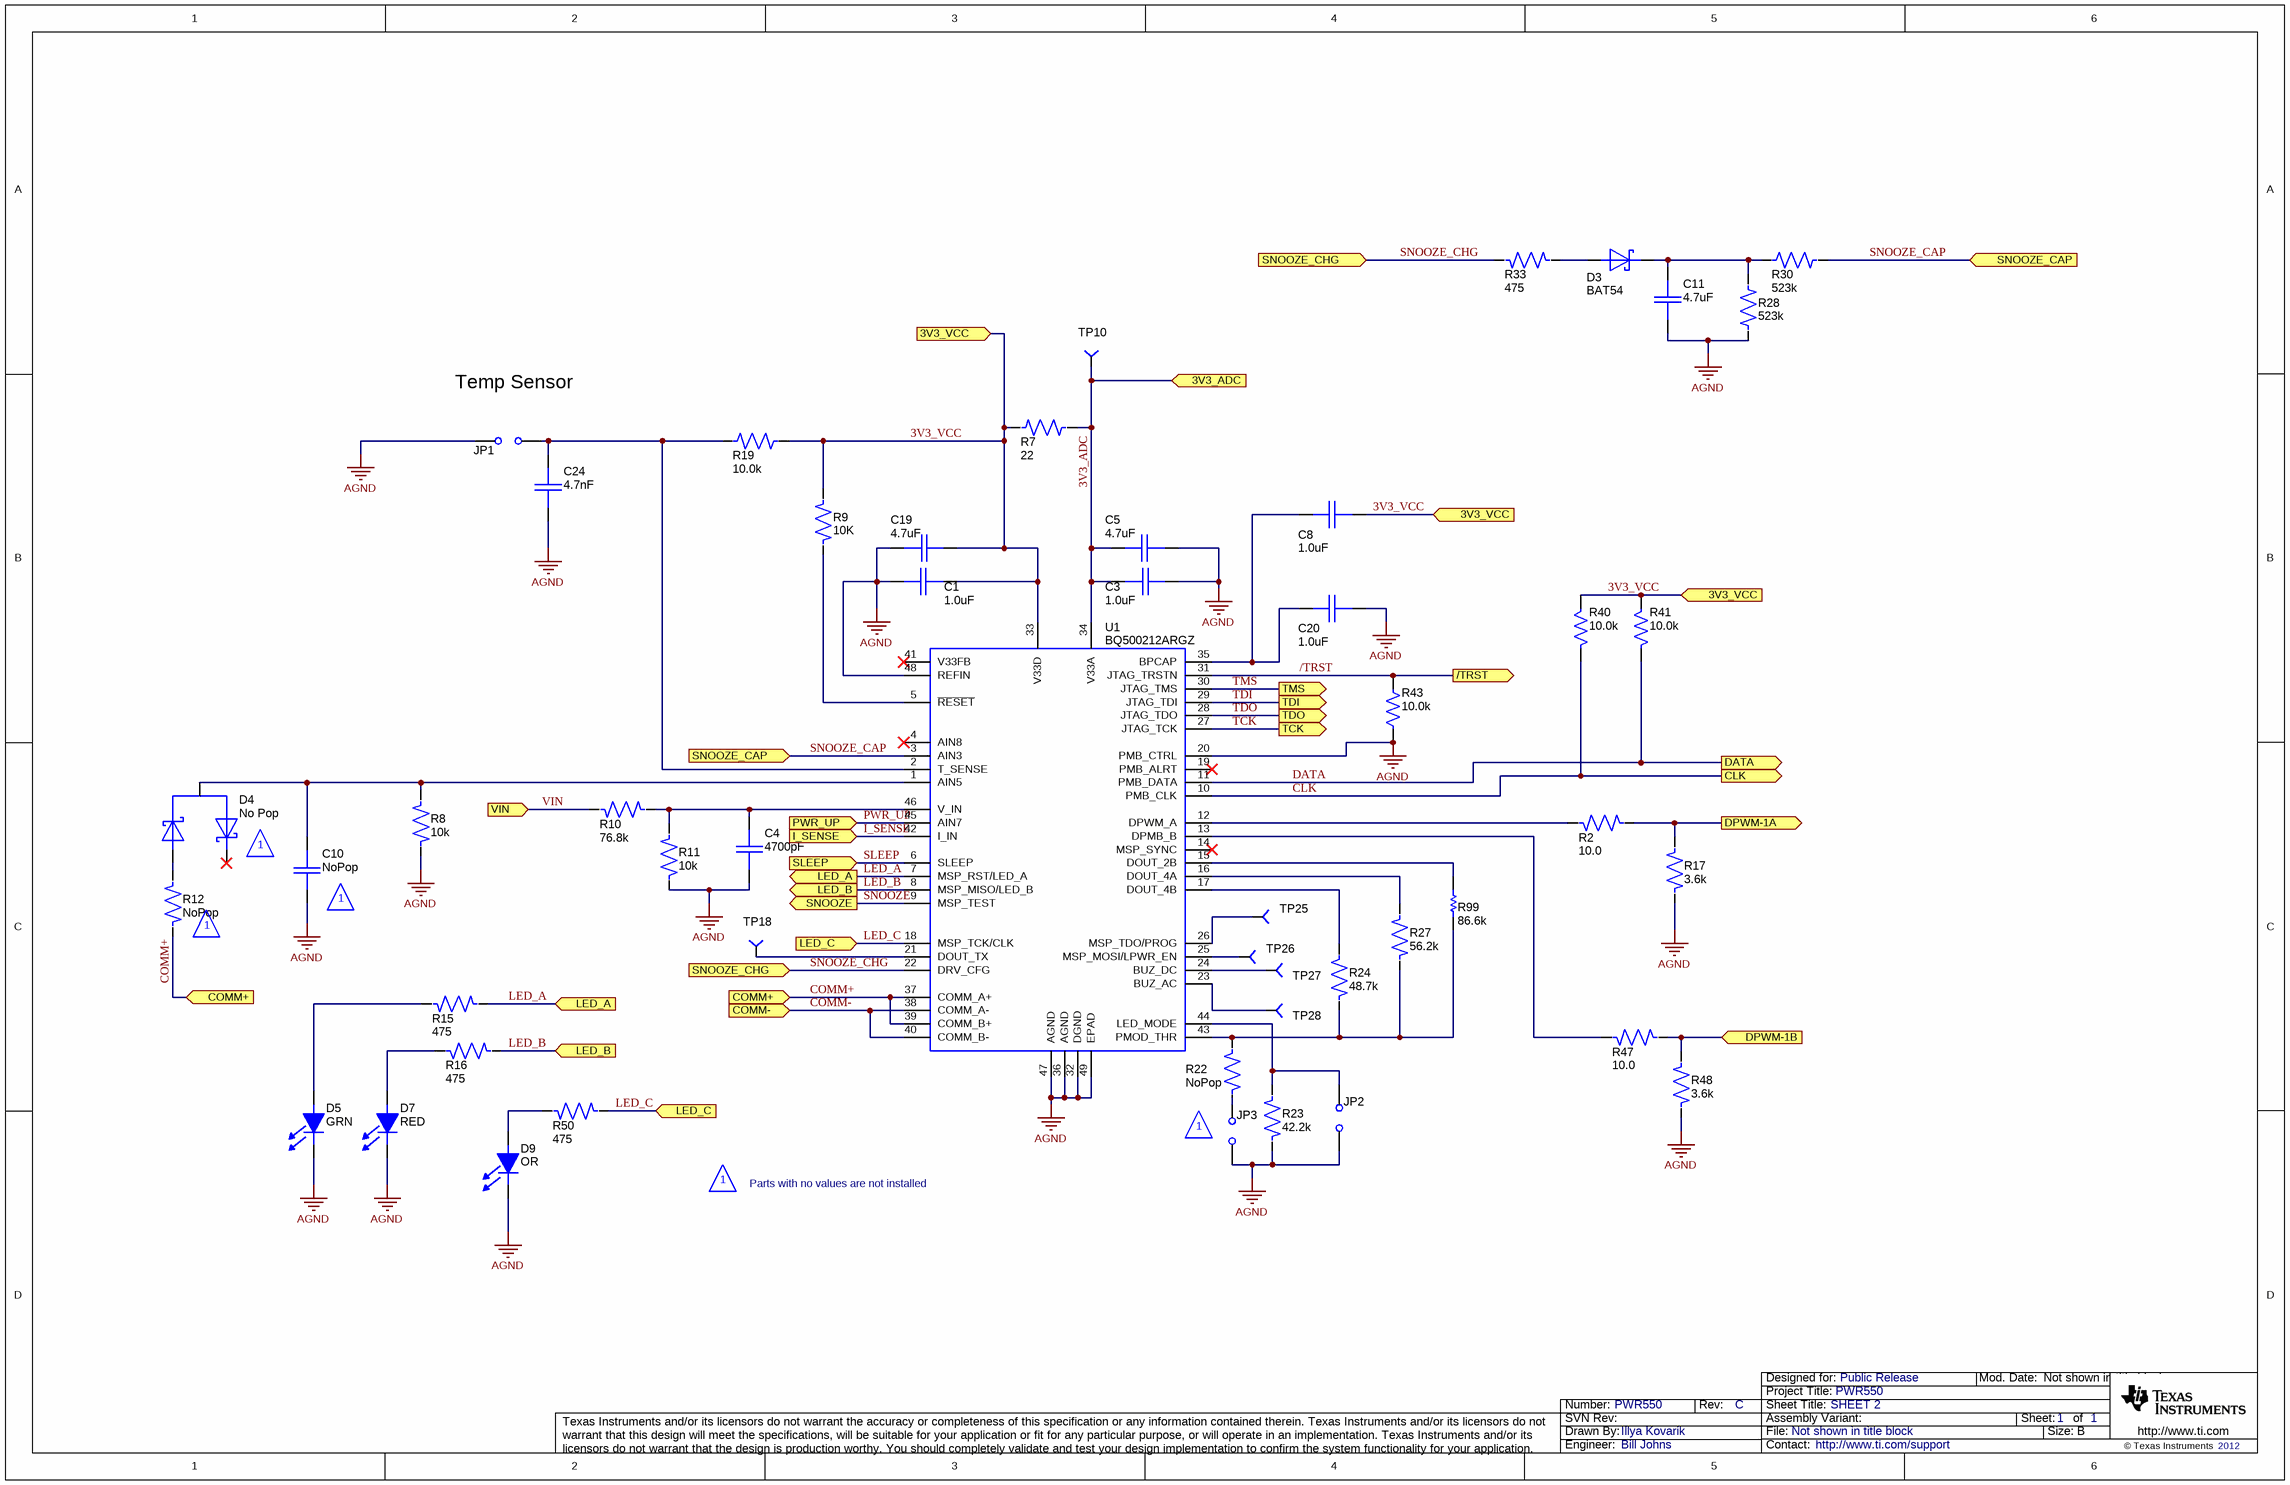
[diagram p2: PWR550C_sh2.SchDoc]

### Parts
C1  value 1.0uF  [C603]  (hidden comment: C0603)
C3  value 1.0uF  [C603]  (hidden comment: C0603)
C4  value 4700pF  [C603]  (hidden comment: C0603)
C5  value 4.7uF  [C603]  (hidden comment: C0603)
C8  value 1.0uF  [C603]  (hidden comment: C0603)
C10  value NoPop  [C603]  (hidden comment: C0603)
C11  value 4.7uF  [C603]  (hidden comment: C0603)
C19  value 4.7uF  [C603]  (hidden comment: C0603)
C20  value 1.0uF  [C603]  (hidden comment: C0603)
C24  value 4.7nF  [C603]  (hidden comment: C0603)
D3  value BAT54  [SOT-23]  (hidden comment: D-BAT54)
D4  value No Pop  [SOT-323]  (hidden comment: D-BAT54SWT1G)
D5  value GRN  [LED-0805]  (hidden comment: D-LED_0805)
D7  value RED  [LED-0805]  (hidden comment: D-LED_0805)
D9  value OR  [LED-0805]  (hidden comment: D-LED_0805)
JP1  JUMPER_2X100MIL  [HDR100_1X2]  (value not drawn)
JP2  JUMPER_2X100MIL  [HDR100_1X2]  (value not drawn)
JP3  JUMPER_2X100MIL  [HDR100_1X2]  (value not drawn)
R2  value 10.0  [R603]  (hidden comment: R0603_1%)
R7  value 22  [R603]  (hidden comment: R0805_1%)
R8  value 10k  [R603]  (hidden comment: R0603_1%)
R9  value 10K  [R603]  (hidden comment: R0603_1%)
R10  value 76.8k  [R603]  (hidden comment: R0603_1%)
R11  value 10k  [R603]  (hidden comment: R0603_1%)
R12  value NoPop  [R603]  (hidden comment: R0603_1%)
R15  value 475  [R603]  (hidden comment: R0603_1%)
R16  value 475  [R603]  (hidden comment: R0603_1%)
R17  value 3.6k  [R603]  (hidden comment: R0603_1%)
R19  value 10.0k  [R603]  (hidden comment: R0603_1%)
R22  value NoPop  [R603]  (hidden comment: R0603_1%)
R23  value 42.2k  [R603]  (hidden comment: R0603_1%)
R24  value 48.7k  [R603]  (hidden comment: R0603_1%)
R27  value 56.2k  [R603]  (hidden comment: R0603_1%)
R28  value 523k  [R603]  (hidden comment: R0603_1%)
R30  value 523k  [R603]  (hidden comment: R0603_1%)
R33  value 475  [R603]  (hidden comment: R0603_1%)
R40  value 10.0k  [R603]  (hidden comment: R0603_1%)
R41  value 10.0k  [R603]  (hidden comment: R0603_1%)
R43  value 10.0k  [R603]  (hidden comment: R0603_1%)
R47  value 10.0  [R603]  (hidden comment: R0603_1%)
R48  value 3.6k  [R603]  (hidden comment: R0603_1%)
R50  value 475  [R603]  (hidden comment: R0603_1%)
R99  value 86.6k  [0603]  (hidden comment: RC0603FR-0786K6L)
TP10  TP_40_SMT  [TP_40_SMT]  (value not drawn)
TP18  TP_40_SMT  [TP_40_SMT]  (value not drawn)
TP25  TP_40_SMT  [TP_40_SMT]  (value not drawn)
TP26  TP_40_SMT  [TP_40_SMT]  (value not drawn)
TP27  TP_40_SMT  [TP_40_SMT]  (value not drawn)
TP28  TP_40_SMT  [TP_40_SMT]  (value not drawn)
U1  value BQ500212ARGZ  [QFN48[RGZ]]  (hidden comment: BQ500210RGZ)

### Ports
3V3_ADC, 3V3_VCC, /TRST, CLK, COMM+, COMM-, DATA, DPWM-1A, DPWM-1B, I_SENSE, LED_A, LED_B, LED_C, PWR_UP, SLEEP, SNOOZE, SNOOZE_CAP, SNOOZE_CHG, TCK, TDI, TDO, TMS, VIN

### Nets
AGND: C1.1 C3.1 C4.2 C5.2 C10.1 C11.2 C19.2 C20.2 C24.2 D5.1(C) D7.1(C) D9.1(C) JP1.2 JP2.1 JP3.2 R8.1 R11.1 R17.1 R23.1 R28.1 R43.1 R48.1 U1.20(PMB_CTRL) U1.32(DGND) U1.36(AGND) U1.47(AGND) U1.48(REFIN) U1.49(EPAD)
3V3_ADC: C3.2 C5.1 R7.2 TP10.1 U1.34(V33A) ; port 3V3_ADC
3V3_VCC: C1.2 C8.2 C19.1 R7.1 R9.2 R19.2 R40.1 R41.1 U1.33(V33D) ; port 3V3_VCC
/TRST: R43.2 U1.31(JTAG_TRSTN) ; port /TRST
CLK: R40.2 U1.10(PMB_CLK) ; port CLK
COMM+: R12.1 U1.37(COMM_A+) U1.39(COMM_B+) ; port COMM+
COMM-: U1.38(COMM_A-) U1.40(COMM_B-) ; port COMM-
DATA: R41.2 U1.11(PMB_DATA) ; port DATA
DPWM-1A: R2.1 R17.2 ; port DPWM-1A
DPWM-1B: R47.1 R48.2 ; port DPWM-1B
I_SENSE: U1.42(I_IN) ; port I_SENSE
LED_A: R15.1 U1.7(MSP_RST/LED_A) ; port LED_A
LED_B: R16.1 U1.8(MSP_MISO/LED_B) ; port LED_B
LED_C: R50.1 U1.18(MSP_TCK/CLK) ; port LED_C
PWR_UP: U1.45(AIN7) ; port PWR_UP
SLEEP: U1.6(SLEEP) ; port SLEEP
SNOOZE: U1.9(MSP_TEST) ; port SNOOZE
SNOOZE_CAP: R30.2 U1.3(AIN3) ; port SNOOZE_CAP
SNOOZE_CHG: R33.2 U1.22(DRV_CFG) ; port SNOOZE_CHG
TCK: U1.27(JTAG_TCK) ; port TCK
TDI: U1.29(JTAG_TDI) ; port TDI
TDO: U1.28(JTAG_TDO) ; port TDO
TMS: U1.30(JTAG_TMS) ; port TMS
VIN: R10.2 ; port VIN
NetC4_1: C4.1 R10.1 R11.2 U1.46(V_IN)
NetC8_1: C8.1 C20.1 U1.35(BPCAP)
NetC10_2: C10.2 D4.3(C-A) R8.2 U1.1(AIN5)
NetC11_1: C11.1 D3.3(C) R28.2 R30.1
NetC24_1: C24.1 JP1.1 R19.1 U1.2(T_SENSE)
NetD3_1: D3.1(A) R33.1
NetD4_1: D4.1(A) R12.2
NetD5_2: D5.2(A) R15.2
NetD7_2: D7.2(A) R16.2
NetD9_2: D9.2(A) R50.2
NetJP2_2: JP2.2 R23.2 U1.44(LED_MODE)
NetJP3_1: JP3.1 R22.1
NetR2_2: R2.2 U1.12(DPWM_A)
NetR9_1: R9.1 U1.5(~{RESET})
NetR22_2: R22.2 R24.1 R27.1 R99.1 U1.43(PMOD_THR)
NetR24_2: R24.2 U1.17(DOUT_4B)
NetR27_2: R27.2 U1.16(DOUT_4A)
NetR47_2: R47.2 U1.13(DPMB_B)
NetR99_2: R99.2 U1.15(DOUT_2B)
NetTP18_1: TP18.1 U1.21(DOUT_TX)
NetTP25_1: TP25.1 U1.26(MSP_TDO/PROG)
NetTP26_1: TP26.1 U1.25(MSP_MOSI/LPWR_EN)
NetTP27_1: TP27.1 U1.24(BUZ_DC)
NetTP28_1: TP28.1 U1.23(BUZ_AC)

Not connected (* = marked no-connect by the designer): D4 2(C)*; U1 4(AIN8)* 14(MSP_SYNC)* 19(PMB_ALRT)* 41(V33FB)*

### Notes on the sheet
- Temp Sensor
- 1
- (near C10) 1
- (near R12) 1
- Parts with no values are not installed

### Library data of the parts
C1 C3 C8 C20 = C0603: as C34 on sheet PWR550C_sh1
C4 = C0603: Capacitor, Ceramic, 4700PF 50V 5% NP0 0603; Manufacturer: TDK; PartNumber: C1608C0G1H472J080AA; Alternate Manufacturer: Digi-Key; Alternate PartNumber: 445-7400-2-ND; Area: 5650
C5 = C0603: Capacitor, Ceramic, 4.7uF, 10V, X7R, 20%; Manufacturer: TDK; PartNumber: CGB3B1X5R1A475M055AC; Area: 5650
C10 = C0603: Capacitor, Ceramic, 50V, C0G, 5%; Manufacturer: TDK; PartNumber: C1608C0G1H330J080AA; Area: 5650
C11 = C0603: as C25 on sheet PWR550C_sh1
C19 = C0603: as C26 on sheet PWR550C_sh1
C24 = C0603: Capacitor, Ceramic, 4.7nF, 50V, X7R, 10%; Manufacturer: TDK; PartNumber: CGA3E2X7R1H472K080AD; Alternate Manufacturer: Digi-Key; Alternate PartNumber: 445-8828-1; Area: 5650
D3 = D-BAT54: as D2 on sheet PWR550C_sh1
D4 = D-BAT54SWT1G: Diode, Dual Schottky, 200mA, 30V; PartNumber: Open; Manufacturer: On Semi; Second Source: C:\program files\p-cad 2004\pcad_pdf's\BAT54SWT1-D.pdf; Area: 11904
D5 = D-LED_0805: Diode. LED 2X1.2MM 568NM GN WTR CLR SMD; PartNumber: APT2012SGC; Manufacturer: Kingbright Corp; Alternate PartNumber: 754-1131-1; Alternate Manufacturer: Digi-Key; Area: 9.85 mm
D7 = D-LED_0805: Diode. LED 2X1.2MM 640NM RD WTR CLR SMD; PartNumber: APT2012SRCPRV; Manufacturer: Kingbright Corp; Alternate PartNumber: 754-1132-1-ND; Alternate Manufacturer: Digi-Key; Area: 9.85 mm
D9 = D-LED_0805: Diode. LED 2X1.2MM 601NM OR WTR CLR SMD; PartNumber: APT2012SECK; Manufacturer: Kingbright Corp; Alternate PartNumber: 754-1130-1; Alternate Manufacturer: Digi-Key; Area: 9.85 mm
JP1 = JUMPER_2X100MIL: Header, Male 2-pin, 100mil spacing,; Manufacturer: Sullins; PartNumber: PEC02SAAN; Second Source: C:\program files\p-cad 2004\pcad_pdf's\pec36saan.pdf; Area: 20000; VALUE: Open
JP2 = JUMPER_2X100MIL: Header, Male 2-pin, 100mil spacing,; Manufacturer: Sullins; PartNumber: PEC02SAAN; Second Source: C:\program files\p-cad 2004\pcad_pdf's\pec36saan.pdf; Area: 20000; VALUE: PEC02SAAN
JP3 = JUMPER_2X100MIL: Header, Male 2-pin, 100mil spacing,; Manufacturer: Sullins; PartNumber: PEC02SAAN; Second Source: C:\program files\p-cad 2004\pcad_pdf's\pec36saan.pdf; area: 20000; Value: Open
R2 R47 = R0603_1%: Resistor, Chip, 10 OHM 1/10W 5% 0603 SMD; Manufacturer: Yageo; PartNumber: RC0603JR-0710RL; Alternate Manufacturer: Digi-Key; Alternate PartNumber: 311-10GR; Area: 9100
R7 = R0805_1%: Resistor, Chip, 22 OHM 1/8W 5% 0805 SMD; Manufacturer: Yageo; PartNumber: RC0805JR-0722RL; Alternate Manufacturer: Digi-Key; Alternate PartNumber: 311-22ARCT; Area: 15,300; PCB DECAL: R0805
R8 R9 R11 R19 R40 R41 R43 = R0603_1%: as R5 on sheet PWR550C_sh1
R10 = R0603_1%: Resistor, Chip, 76.8K OHM 1/10W 1% 0603 SMD; Manufacturer: Yageo; PartNumber: RC0603FR-0776K8L; Alternate Manufacturer: Digi-Key; Alternate PartNumber: 311-76.8KHRCT; Area: 9100
R12 = R0603_1%: Resistor, Chip, 1/16W, 1%; PartNumber: Open; Area: 9100
R15 R16 = R0603_1%: Resistor, Chip, 475 OHM 1/10W 1% 0603 SMD; Manufacturer: Yageo; PartNumber: RC0603FR-07475RL; Alternate Manufacturer: Digi-Key; Alternate PartNumber: 311-475HRCT; Area: 9100
R17 = R0603_1%: Resistor, Chip,  3.60K OHM 1/10W 1% 0603 SMD; Manufacturer: Yageo; PartNumber: RC0603FR-073K6L; Alternate Manufacturer: Digi-Key; Alternate PartNumber: 311-3.60KHR; Area: 9100
R22 = R0603_1%: Resistor, Chip,  56.2K OHM 1/10W 1% 0603 SMD; Manufacturer: Yageo; PartNumber: RC0603FR-0756K2L; Alternate Manufacturer: Digi-Key; Alternate PartNumber: 311-56.2KHRCT; Area: 9100
R23 = R0603_1%: Resistor, Chip, 42.2K OHM 1/10W 1% 0603 SMD; Manufacturer: Yageo; PartNumber: RC0603FR-0742K2L; Alternate PartNumber: 311-42.2KHRCT; Description: Resistor, Chip, 56.2K OHM 1/10W 1% 0603 SMD; Area: 9100
R24 = R0603_1%: Resistor, Chip, 1/16W, 1%; Manufacturer: Yageo; PartNumber: RC0603FR-0748K7L; Alternate Manufacturer: DigiKey; Alternate PartNumber: 311-48.7KHRCT-ND; Area: 9100
R27 = R0603_1%: Resistor, Chip, 56.2K OHM 1/10W 1%; Manufacturer: Yageo; PartNumber: RC0603FR-0756K2L; Alternate Manufacturer: Digi-Key; Alternate PartNumber: 311-56.2KHRCT-ND; Area: 9100
R28 R30 = R0603_1%: as R25 on sheet PWR550C_sh1
R33 = R0603_1%: Resistor, Chip, 475 OHM 1/10W 1% 0603 SMD; Manufacturer: Yageo; PartNumber: RC0603FR-07475RL; Alternate Manufacturer: Digi-Key; Alternate PartNumber: 311-475HRC; Area: 9100
R48 = R0603_1%: Resistor, Chip, 3.60K OHM 1/10W 1% 0603 SMD; Manufacturer: Yageo; PartNumber: RC0603FR-073K6L; Alternate Manufacturer: Digi-Key; Alternate PartNumber: 311-3.60KHRCT; Area: 9100
R50 = R0603_1%: Resistor, Chip,  475 OHM 1/10W 1% 0603 SMD; Manufacturer: Yageo; PartNumber: RC0603FR-07475RL; Alternate Manufacturer: Digi-Key; Alternate PartNumber: 311-475HRCT; Area: 9100
R99 = RC0603FR-0786K6L: RES, 86.6k ohm, 1%, 0.1W, 0603; Manufacturer: Yageo America; CompType: Resistor; Res_ohm: 86600; Value_Code: 86k6; Tolerance_%: 1; Power_W: 0.1; VDC_V: 150; TempCo: 200 ppm/C; EIA_Code: E96; U/M: EA
TP10 TP18 TP25-TP28 = TP_40_SMT: as TP9 on sheet PWR550C_sh1
U1 = BQ500210RGZ: IC, Qi Compliant Wireless Power Transmitter Manager; Manufacturer: TI; Alternate Manufacturer: None; Second Source: \\vette02\pmp_pcb\pcad_pdf's\Harpoon-PS.pdf; Area: 115600

## Sheet PWR550C_sh3.SchDoc: SHEET 3
size 431 x 279 mm; Date: Not shown in title block; ApprovedBy: Not shown in title block; CheckedBy: Not shown in title block; Author: Not shown in title block; CompanyName: Not shown in title block; DrawnBy: Illya Kovarik; Engineer: Not shown in title block; Organization: Not shown in title block; Address1: Not shown in title block; Address2: Not shown in title block; Address3: Not shown in title block; Address4: Not shown in title block; DocumentNumber: 1; Revision: Use project parameter SCH_Rev; SheetNumber: 1; SheetTotal: 1; PageSetup: Record=PageOptions|CenterHorizontal=True|CenterVertical=True|PrintScale=1.00|XCorrection=1.00|YCorrection=1.00|PrintKind=0|BorderSize=5000000|LeftOffset=0|BottomOffset=0|Orientation=2|PaperLength=1000|PaperWidth=1000|Scale=100|PaperSource=15|PrintQuality=600|MediaType=1|DitherType=10|PaperKind=Letter|PrintScaleMode=1
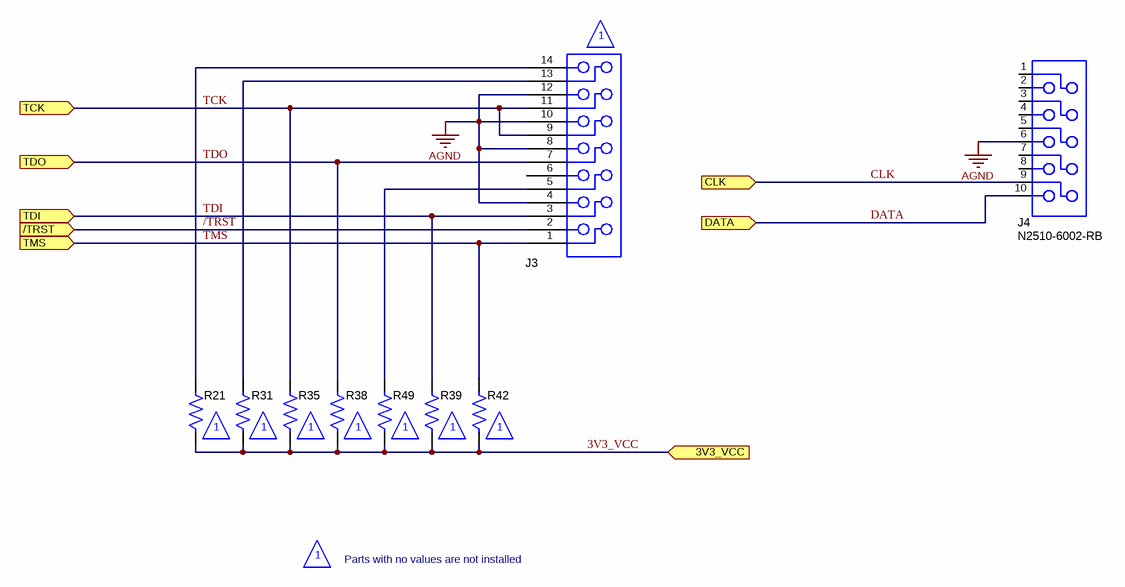
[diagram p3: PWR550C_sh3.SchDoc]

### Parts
J3  HEADER_14PJTAG  [HEADER_2500_]  (value not drawn)
J4  value N2510-6002-RB  [CONN_2510-6002UB]  (hidden comment: CONN_2510-6002UB)
R21  R0603_1%  [R603]  (value not drawn)
R31  R0603_1%  [R603]  (value not drawn)
R35  R0603_1%  [R603]  (value not drawn)
R38  R0603_1%  [R603]  (value not drawn)
R39  R0603_1%  [R603]  (value not drawn)
R42  R0603_1%  [R603]  (value not drawn)
R49  R0603_1%  [R603]  (value not drawn)

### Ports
3V3_VCC, /TRST, CLK, DATA, TCK, TDI, TDO, TMS

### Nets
AGND: J3.4 J3.8 J3.10 J3.12 J4.6
3V3_VCC: R21.1 R31.1 R35.1 R38.1 R39.1 R42.1 R49.1 ; port 3V3_VCC
/TRST: J3.2 ; port /TRST
CLK: J4.9 ; port CLK
DATA: J4.10 ; port DATA
TCK: J3.9 J3.11 R35.2 ; port TCK
TDI: J3.3 R39.2 ; port TDI
TDO: J3.7 R38.2 ; port TDO
TMS: J3.1 R42.2 ; port TMS
NetJ3_5: J3.5 R49.2
NetJ3_13: J3.13 R31.2
NetJ3_14: J3.14 R21.2

Not connected (* = marked no-connect by the designer): J3 6; J4 1 2 3 4 5 7 8

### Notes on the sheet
- (near J3) 1
- 1
- (near R42) 1
- Parts with no values are not installed

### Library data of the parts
J3 = HEADER_14PJTAG: Header, 2x7 pin, 100mil spacing, Straight, 4 Wall; Manufacturer: 3M; PartNumber: N2514-6002-RB; Second Source: C:\program files\p-cad 2004\pcad_pdf's\3M_2514 series.pdf; area: 374624; Value: Open
J4 = CONN_2510-6002UB: Connector, Male Straight 2x5 pin, 100mil spacing, 4 Wall; Manufacturer: 3M; PartNumber: N2510-6002RB; Second Source: C:\program files\p-cad 2004\pcad_pdf's\2500%20Series.pdf; area: 301.024
R21 R31 R35 R38 R39 R42 R49 = R0603_1%: Resistor, Chip, 1/16W, 1%; PartNumber: Open; Area: 9100; Value: Open

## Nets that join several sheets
AGND: PWR550C_sh1 (24 pins), PWR550C_sh2 (28 pins), PWR550C_sh3 (5 pins)
3V3_VCC: PWR550C_sh1 (6 pins), PWR550C_sh2 (9 pins), PWR550C_sh3 (7 pins)
/TRST: PWR550C_sh2 (R43.2 U1.31), PWR550C_sh3 (J3.2)
CLK: PWR550C_sh2 (R40.2 U1.10), PWR550C_sh3 (J4.9)
COMM+: PWR550C_sh1 (R29.2 TP13.1), PWR550C_sh2 (R12.1 U1.37 U1.39)
COMM-: PWR550C_sh1 (R26.1), PWR550C_sh2 (U1.38 U1.40)
DATA: PWR550C_sh2 (R41.2 U1.11), PWR550C_sh3 (J4.10)
DPWM-1A: PWR550C_sh1 (TP3.1 U2.8), PWR550C_sh2 (R2.1 R17.2)
DPWM-1B: PWR550C_sh1 (TP2.1 U3.8), PWR550C_sh2 (R47.1 R48.2)
I_SENSE: PWR550C_sh1 (C16.2 R46.1 TP19.1), PWR550C_sh2 (U1.42)
PWR_UP: PWR550C_sh1 (R45.1), PWR550C_sh2 (U1.45)
SLEEP: PWR550C_sh1 (Q7.1 R52.2 TP20.1), PWR550C_sh2 (U1.6)
SNOOZE: PWR550C_sh1 (Q4.1 R18.2 TP14.1), PWR550C_sh2 (U1.9)
TCK: PWR550C_sh2 (U1.27), PWR550C_sh3 (J3.9 J3.11 R35.2)
TDI: PWR550C_sh2 (U1.29), PWR550C_sh3 (J3.3 R39.2)
TDO: PWR550C_sh2 (U1.28), PWR550C_sh3 (J3.7 R38.2)
TMS: PWR550C_sh2 (U1.30), PWR550C_sh3 (J3.1 R42.2)
VIN: PWR550C_sh1 (21 pins), PWR550C_sh2 (R10.2)

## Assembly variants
001: not fitted C10 C12 D4 D8 J3 JP3 L1 L3 R12 R21 R22 R31 R35 R38 R39 R42 R49 SH-J1 TP2 TP3 TP9 TP10 TP13 TP14 TP18 TP19 TP20 TP25 TP26 TP27 TP28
